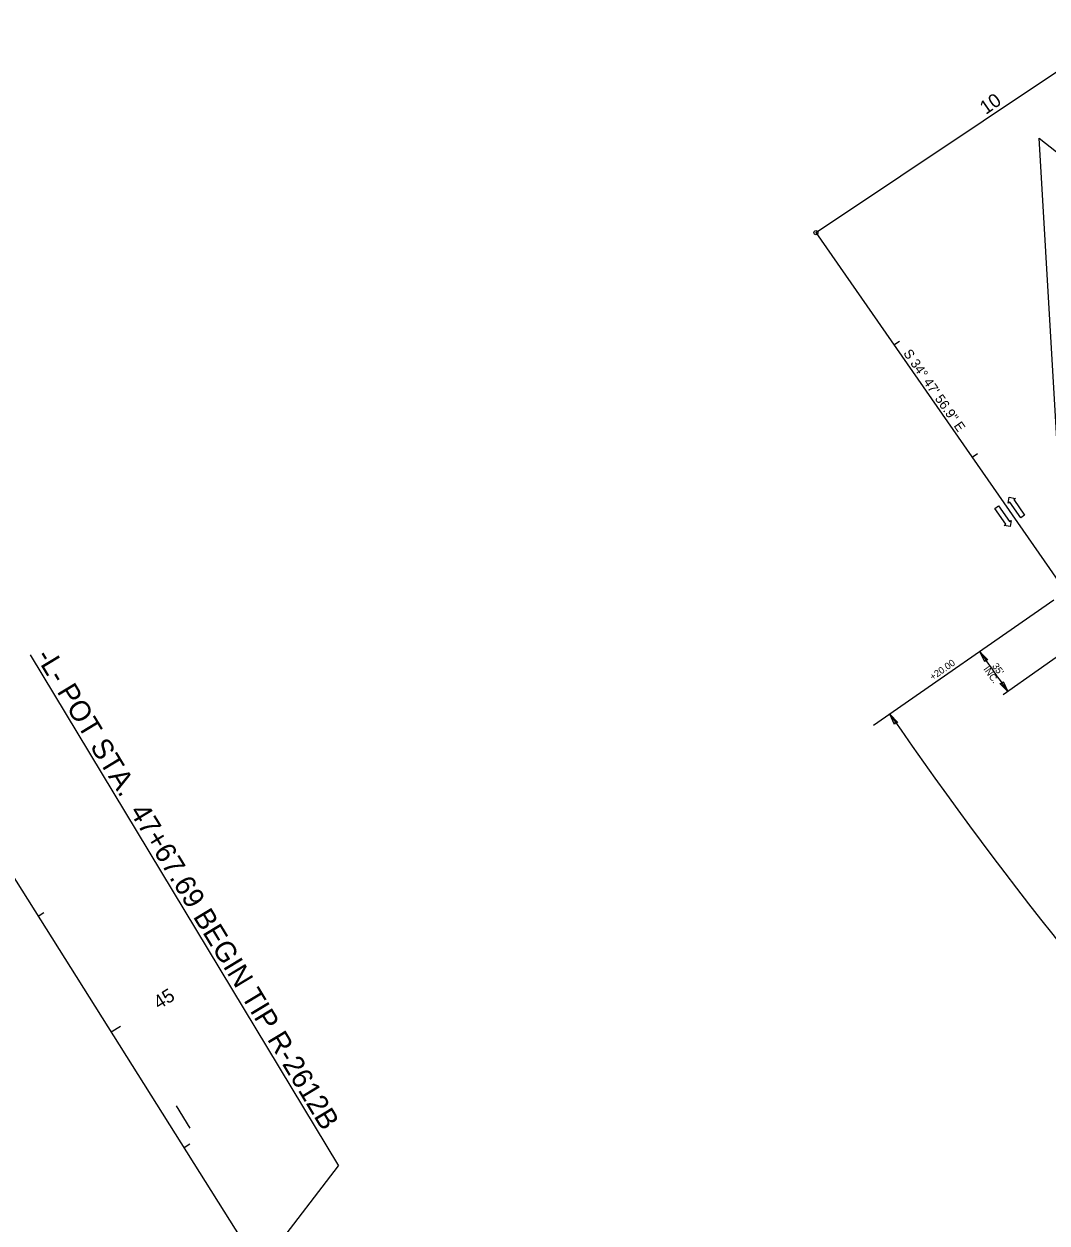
# Model space of a CAD drawing. Extents: x 1778969 to 1790720, y 807089 to 817794.
# Drawn here: x 1781066 to 1781814, y 814616 to 815493 of the extents above; entities that cross this region are included whole.
import ezdxf

# ---------------------------------------------------------------- set-up
doc = ezdxf.new("R2010")
doc.units = 0
for name, color, linetype in [('Default', 7, 'Continuous'), ('Prop Dimension', 7, 'Continuous'), ('Prop Dimension Text', 7, 'Continuous'), ('Prop Horizontal Alignment', 7, 'Continuous'), ('Prop Horizontal Alignment Direction Label', 7, 'Continuous'), ('Prop Horizontal Alignment Station Label', 7, 'Continuous'), ('Prop Horizontal Alignment Tick Label', 7, 'Continuous'), ('Prop Horizontal Alignment Tick Large', 7, 'Continuous'), ('Prop Horizontal Alignment Tick Small', 7, 'Continuous'), ('Prop Lane Arrow CELL', 7, 'Continuous'), ('Prop Terminator CELL', 7, 'Continuous')]:
    doc.layers.add(name, color=color, linetype=linetype)

msp = doc.modelspace()

# ---------------------------------------------------------------- linework, layer by layer
at = {"layer": 'Default'}
msp.add_line((1781176.9, 814701.73), (1781186.99, 814685.56), dxfattribs=at)
at = {"layer": 'Prop Dimension'}
for p, q in [((1781818.55, 815071.48), (1781686.85, 814979.95)), ((1781832.62, 815038.46), (1781781.53, 815002.33))]:
    msp.add_line(p, q, dxfattribs=at)
for centre, radius, start, end in [((1784206.85, 816717.33), 2966.25, 214.57857, 215.26503), ((1784215.14, 816723.19), 3056.56, 214.58509, 223.1679)]:
    msp.add_arc(centre, radius, start, end, dxfattribs=at)
at = {"layer": 'Prop Horizontal Alignment'}
for p, q in [((1780487.95, 815773.73), (1781812.35, 813671.96)), ((1780487.95, 815773.73), (1781812.35, 813671.96)), ((1781644.64, 815340.3), (1781833.78, 815068.16))]:
    msp.add_line(p, q, dxfattribs=at)
at = {"layer": 'Prop Horizontal Alignment Station Label'}
for p, q in [((1781645.87, 815341.16), (1781827.87, 815462.64)), ((1781827.26, 815077.53), (1781807.83, 815409.38)), ((1781807.83, 815409.38), (1781943.15, 815302.75)), ((1781070.22, 815031.59), (1781295.69, 814658.05)), ((1781143.14, 814459.33), (1781295.69, 814658.05))]:
    msp.add_line(p, q, dxfattribs=at)
msp.add_circle((1781644.64, 815340.3), 1.5, dxfattribs=at)
at = {"layer": 'Prop Horizontal Alignment Tick Large'}
for p, q in [((1781644.64, 815340.3), (1781651.21, 815344.87)), ((1781129.33, 814755.88), (1781136.1, 814760.15))]:
    msp.add_line(p, q, dxfattribs=at)
at = {"layer": 'Prop Horizontal Alignment Tick Small'}
for p, q in [((1781701.71, 815258.19), (1781705.81, 815261.04)), ((1781758.78, 815176.07), (1781762.88, 815178.93)), ((1781076.02, 814840.49), (1781080.25, 814843.15)), ((1781182.64, 814671.28), (1781186.87, 814673.95))]:
    msp.add_line(p, q, dxfattribs=at)
at = {"layer": 'Prop Lane Arrow CELL'}
for p, q in [((1781775.47, 815138.59), (1781778.18, 815140.48)), ((1781778.18, 815140.48), (1781786.17, 815128.98)), ((1781785.3, 815142.43), (1781786.05, 815146.79)), ((1781786.53, 815143.29), (1781785.3, 815142.43)), ((1781786.05, 815146.79), (1781790.47, 815146.03)), ((1781794.52, 815131.79), (1781786.53, 815143.29)), ((1781790.47, 815146.03), (1781789.24, 815145.17)), ((1781789.24, 815145.17), (1781797.23, 815133.68)), ((1781783.46, 815127.1), (1781775.47, 815138.59)), ((1781797.23, 815133.68), (1781794.52, 815131.79)), ((1781782.23, 815126.24), (1781783.46, 815127.1)), ((1781786.65, 815125.48), (1781782.23, 815126.24)), ((1781786.17, 815128.98), (1781787.4, 815129.84)), ((1781787.4, 815129.84), (1781786.65, 815125.48))]:
    msp.add_line(p, q, dxfattribs=at)
at = {"layer": 'Prop Terminator CELL'}
for points in [[(1781768.07, 815026.43), (1781764.59, 815033.88), (1781770.42, 815028.01), (1781768.65, 815028.04)], [(1781781.52, 815012.22), (1781784.93, 815004.74), (1781779.15, 815010.65), (1781780.93, 815010.61)], [(1781702.06, 814980.69), (1781698.72, 814988.2), (1781704.44, 814982.22), (1781702.67, 814982.29)]]:
    msp.add_lwpolyline(points, close=True, dxfattribs=at)

# ---------------------------------------------------------------- texts
at = {"layer": 'Prop Dimension Text'}
for s, rotation, p in [('+20.00', 35.12089, (1781730.09, 815012.76)), ("35'", 305.79545, (1781773.25, 815023.34)), ('INC.', 305.79545, (1781766.79, 815021.09))]:
    msp.add_text(s, height=5, rotation=rotation, dxfattribs=at).set_placement(p)
at = {"layer": 'Prop Horizontal Alignment Direction Label'}
msp.add_text('S 34%%d 47\' 56.9" E', height=7, rotation=304.79915, dxfattribs=at).set_placement((1781708.27, 815252.08))
at = {"layer": 'Prop Horizontal Alignment Station Label'}
msp.add_text('-L- POT STA.  47+67.69 BEGIN TIP R-2612B', height=15, rotation=301.16518, dxfattribs=at).set_placement((1781073.79, 815030.57))
at = {"layer": 'Prop Horizontal Alignment Tick Label'}
for s, rotation, p in [('10', 34.79915, (1781768.88, 815426.29)), ('45', 32.21667, (1781164.28, 814772))]:
    msp.add_text(s, height=10, rotation=rotation, dxfattribs=at).set_placement(p)

doc.saveas('drawing.dxf')
